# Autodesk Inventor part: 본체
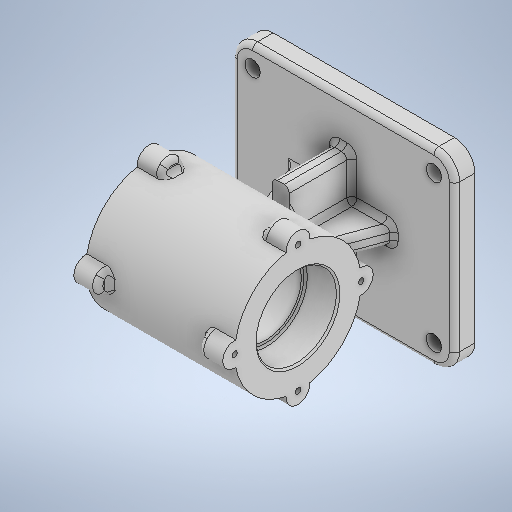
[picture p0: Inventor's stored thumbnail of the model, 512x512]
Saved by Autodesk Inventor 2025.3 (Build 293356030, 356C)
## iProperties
Created: 2025-08
Part Number: 본체
Material: 일반
Document SubType Name: Modeling
Designer: infra011
Density: 1 g/cm^3
Appearance: 기본값
Author: infra011
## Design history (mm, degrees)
sketch "스케치1"
  geometry: L1 (-65, 55)-(65, 55); L2 (65, 55)-(65, -55); L3 (65, -55)-(-65, -55); L4 (-65, -55)-(-65, 55); L5 (-65, 55)-(65, -55); L6 (65, 55)-(-65, -55); 1 further point
  constraints: 12 end point, 2 midpoint, 2 parallel, 1 horizontal, 1 perpendicular
  dimensions: "d0" = 130 distance of L2.end L3.end; "d1" = 110 distance of L1.end L2.end
extrude "돌출1" new body sketch "스케치1" distance "d2" = 12; taper "d3" = 0 deg
sketch "스케치2"
  geometry: L1 (-53, 43)-(53, 43); L2 (53, 43)-(53, -43); L3 (53, -43)-(-53, -43); L4 (-53, -43)-(-53, 43); L5 (-53, 43)-(53, -43); L6 (53, 43)-(-53, -43); 1 further point
  constraints: 12 end point, 2 midpoint, 2 parallel, 1 horizontal, 1 perpendicular
  dimensions: "d4" = 106 distance of L2.end L3.end; "d5" = 86 distance of L1.end L2.end
hole "구멍1" sketch "스케치2" at (-53, 43), (53, -43), (53, 43), (-53, -43) diameter "d6" = 9; stored, may be unused: countersink angle "d10" = 90 deg, drill point angle "d12" = 0 deg; dims "d7" = 8, "d8" = 4, "d9" = 2, "d11" = 12
sketch "스케치3"
  geometry: L1 (43.5, 119)-(-43.5, 119); L2 (-43.5, 119)-(-43.5, 82); L3 (-43.5, 82)-(43.5, 82); L4 (43.5, 82)-(43.5, 119); L5 (43.5, 119)-(-43.5, 82); L6 (-43.5, 119)-(43.5, 82); L7 (65, 0)-(-65, 0) reference; 5 further points
  constraints: 12 end point, 5 midpoint, 2 parallel, 1 horizontal, 1 perpendicular, 1 vertical alignment
  dimensions: "d14" = 37 distance of L1.end L2.end; "d15" = 87 distance of L1.start L1.end; "d16" = 82 distance of point (0, 0) point (0, 82)
revolve "회전1" sketch "스케치3" stored, may be unused: angle "d17" = 90 deg
sketch "스케치4"
  geometry: L1 (43.5, 45)-(43.5, 119) reference; L2 (43.5, 105.5)-(24.5, 105.5); L3 (24.5, 105.5)-(24.5, 82); L4 (24.5, 82)-(43.5, 82); L5 (43.5, 82)-(43.5, 105.5); L6 (24.5, 103)-(-24.5, 103); L7 (-24.5, 103)-(-24.5, 82); L8 (-24.5, 82)-(24.5, 82); L9 (24.5, 82)-(24.5, 103); L10 (-24.5, 105.5)-(-43.5, 105.5); L11 (-43.5, 105.5)-(-43.5, 82); L12 (-43.5, 82)-(-24.5, 82); L13 (-24.5, 82)-(-24.5, 105.5); L14 (-43.5, 45)-(-43.5, 119) reference; L15 (43.5, 45)-(43.5, 119) reference; L16 (-43.5, 45)-(43.5, 45) reference; 4 further points
  constraints: 24 end point, 6 parallel, 3 horizontal, 3 perpendicular, 2 collinear, 2 point on line
  dimensions: "d18" = 19 distance between parallel lines of L5 L9; "d19" = 19 distance between parallel lines of L14 L7; "d20" = 21 distance between parallel lines of L8 L6; "d21" = 23.5 distance between parallel lines of L4 L2; "d22" = 23.5 distance between parallel lines of L12 L10; "d23" = 37 distance between parallel lines of L16 L4; "d24" = 37 distance between parallel lines of L16 L12
revolve "회전2" sketch "스케치4" stored, may be unused: angle "d25" = 90 deg
sketch "스케치5"
  geometry: L1 (0, 0)-(37, 0); C1 r 23.5 at (0, 0) reference; C2 r 7 at (37, 0); C3 r 7 at (0, 37); C4 r 7 at (-37, 0); C5 r 7 at (0, -37); 13 further points
  constraints: 5 coincident, 4 centre point, 2 end point, 1 horizontal, 15 other
  dimensions: "d26" = 14 diameter of C2; "d29" = 360 deg dimension on C1.centre C2.centre (derived)
extrude "돌출2" join sketch "스케치5" distance "d31" = 14; taper "d32" = 0 deg
sketch "스케치6"
  geometry: C1 r 23.5 at (0, 0) reference; C2 r 37 at (0, 0) reference; C3 r 7 at (-37, 0); C4 r 7 at (0, 37); C5 r 7 at (37, 0); C6 r 7 at (0, -37); A1 r 37 centre (0, 0) between (-36.338, 6.969) and (-36.338, -6.969) reference; A2 r 7 centre (-37, 0) between (-36.338, 6.969) and (-36.338, -6.969) reference; A3 r 37 centre (0, 0) between (6.969, 36.338) and (-6.969, 36.338) reference; A4 r 7 centre (0, 37) between (6.969, 36.338) and (-6.969, 36.338) reference; A5 r 37 centre (0, 0) between (36.338, -6.969) and (36.338, 6.969) reference; A6 r 7 centre (37, 0) between (36.338, -6.969) and (36.338, 6.969) reference; A7 r 37 centre (0, 0) between (-6.969, -36.338) and (6.969, -36.338) reference; A8 r 7 centre (0, -37) between (-6.969, -36.338) and (6.969, -36.338) reference; 8 further points
  constraints: 4 centre point, 4 coincident, 1 point on circle
  dimensions: "d33" = 14 diameter of C6; "d34" = 14 diameter of C4; "d35" = 14 diameter of C3; "d36" = 14 diameter of C5
extrude "돌출3" join sketch "스케치6" distance "d37" = 14; taper "d38" = 0 deg
fillet "모깎기1" dims "d39" = 1
chamfer "모따기1" distance "d40" = 1; stored, may be unused: second distance "d41" = 2, angle "d42" = 45 deg
chamfer "모따기2" distance "d43" = 1; stored, may be unused: second distance "d44" = 2, angle "d45" = 45 deg
sketch "스케치7"
  geometry: L1 (43.5, 88.969)-(29.5, 88.969) reference; L2 (29.5, 88.969)-(29.5, 75.031) reference; L3 (29.5, 75.031)-(43.5, 75.031) reference; L4 (43.5, 45.662)-(43.5, 75.031) reference; L5 (43.5, 45.662)-(29.5, 45.662) reference; L6 (29.5, 45.662)-(29.5, 45.662) reference; L7 (29.5, 45.662)-(43.5, 45.662) reference; L8 (43.5, 75.031)-(43.5, 45.662) reference; L9 (43.5, 75.031)-(29.5, 75.031) reference; L10 (29.5, 75.031)-(29.5, 88.969) reference; L11 (29.5, 88.969)-(43.5, 88.969) reference; L12 (43.5, 118.338)-(43.5, 88.969) reference; L13 (43.5, 118.338)-(29.5, 118.338) reference; L14 (29.5, 118.338)-(29.5, 118.338) reference; L15 (29.5, 118.338)-(43.5, 118.338) reference; L16 (43.5, 88.969)-(43.5, 118.338) reference; L17 (-43.5, 45.662)-(-29.5, 45.662) reference; L18 (-29.5, 45.662)-(-29.5, 45.662) reference; L19 (-29.5, 45.662)-(-43.5, 45.662) reference; L20 (-43.5, 45.662)-(-43.5, 75.031) reference; L21 (-43.5, 75.031)-(-29.5, 75.031) reference; L22 (-29.5, 75.031)-(-29.5, 88.969) reference; L23 (-29.5, 88.969)-(-43.5, 88.969) reference; L24 (-43.5, 88.969)-(-43.5, 118.338) reference; L25 (-43.5, 118.338)-(-29.5, 118.338) reference; L26 (-29.5, 118.338)-(-29.5, 118.338) reference; L27 (-29.5, 118.338)-(-43.5, 118.338) reference; L28 (-43.5, 118.338)-(-43.5, 88.969) reference; L29 (-43.5, 88.969)-(-29.5, 88.969) reference; L30 (-29.5, 88.969)-(-29.5, 75.031) reference; L31 (-29.5, 75.031)-(-43.5, 75.031) reference; L32 (-43.5, 75.031)-(-43.5, 45.662) reference; L33 (-29.5, 45)-(29.5, 45) reference; L34 (-65, 0)-(65, 0) reference; L35 (48.5, 12)-(57.5, 12) reference; L36 (-57.5, 12)-(-48.5, 12) reference; L37 (-57.5, 12)-(-48.5, 12) reference; L38 (48.5, 12)-(57.5, 12) reference; L39 (65, 12)-(-65, 12) reference; L40 (-65, 12)-(65, 12) reference; L41 (30, 12)-(17.44, 46.508); L42 (-17.338, 46.787)-(-30, 12); L43 (30, 12)-(-30, 12); L44 (17.44, 46.508)-(-17.338, 46.787); 7 further points
  constraints: 8 end point, 2 midpoint, 2 point on line, 1 collinear, 1 vertical alignment
  dimensions: "d46" = 60 distance of L42.end L41.start; "d47" = 110 deg angle of L39 L41; "d48" = 110 deg angle of L39 L42; "d50" = 30 horizontal distance of point (0, 45) L41.start
extrude "돌출4" join sketch "스케치7" stored distance "d51" = 10; taper "d52" = 0 deg
sketch "스케치9"
  geometry: L1 (-5, -30)-(5, -30); L2 (5, -30)-(5, 30); L3 (5, 30)-(-5, 30); L4 (-5, 30)-(-5, -30); L5 (-65, -55)-(65, -55) reference; 3 further points
  constraints: 8 end point, 2 midpoint, 2 parallel, 1 horizontal, 1 horizontal alignment, 1 perpendicular, 1 vertical alignment
  dimensions: "d59" = 10 distance of L2.end L3.end; "d62" = 60 distance between parallel lines of L3 L1
extrude "돌출6" join sketch "스케치9" distance "d63" = 36.5; taper "d64" = 0 deg
fillet "모깎기2" dims "d65" = 12
fillet "모깎기3" dims "d66" = 3
sketch "스케치10"
  geometry: C1 r 24.5 at (-37, 0) reference; A1 r 37 centre (-37, 0) between (-73.338, -6.969) and (-43.969, -36.338) reference; A2 r 7 centre (-37, -37) between (-43.969, -36.338) and (-30.031, -36.338) reference; A3 r 37 centre (-37, 0) between (-30.031, -36.338) and (-0.662, -6.969) reference; A4 r 7 centre (0, 0) between (-0.662, -6.969) and (-0.662, 6.969) reference; A5 r 37 centre (-37, 0) between (-0.662, 6.969) and (-30.031, 36.338) reference; A6 r 7 centre (-37, 37) between (-30.031, 36.338) and (-43.969, 36.338) reference; A7 r 37 centre (-37, 0) between (-43.969, 36.338) and (-73.338, 6.969) reference; A8 r 7 centre (-74, 0) between (-73.338, 6.969) and (-73.338, -6.969) reference; 1 further point
hole "구멍2" sketch "스케치10" at (-74, 0), (-37, 37), (0, 0), (-37, -37) diameter "d67" = 3.242; stored, may be unused: countersink angle "d71" = 90 deg, drill point angle "d73" = 118 deg; dims "d68" = 8, "d69" = 4, "d70" = 2, "d72" = 10
fillet "모깎기4" dims "d74" = 3
sketch "스케치11"
  geometry: C1 r 24.5 at (37, 0) reference; A1 r 37 centre (37, 0) between (73.338, 6.969) and (43.969, 36.338) reference; A2 r 7 centre (37, 37) between (43.969, 36.338) and (30.031, 36.338) reference; A3 r 37 centre (37, 0) between (30.031, 36.338) and (0.662, 6.969) reference; A4 r 7 centre (0, 0) between (0.662, 6.969) and (0.662, -6.969) reference; A5 r 37 centre (37, 0) between (0.662, -6.969) and (30.031, -36.338) reference; A6 r 7 centre (37, -37) between (30.031, -36.338) and (43.969, -36.338) reference; A7 r 37 centre (37, 0) between (43.969, -36.338) and (73.338, -6.969) reference; A8 r 7 centre (74, 0) between (73.338, -6.969) and (73.338, 6.969) reference; 1 further point
hole "구멍3" sketch "스케치11" at (37, -37), (0, 0), (37, 37), (74, 0) diameter "d75" = 3.242; stored, may be unused: countersink angle "d79" = 90 deg, drill point angle "d81" = 118 deg; dims "d76" = 8, "d77" = 4, "d78" = 2, "d80" = 10
node "솔리드1"
node "투영된 루프1"
node "투영된 루프2"
node "스케치 - 원형 패턴1" dims "d29" = 360 deg (derived)
node "투영된 루프3"
node "투영된 루프4"
node "투영된 루프5"
node "투영된 루프6"
node "투영된 루프7"
node "투영된 루프8"
node "투영된 루프9"
node "투영된 루프10"
feature "A9D066F2-1C7D-4E18-AEED-F7BC21143FA4" dims "d6" = 9, "d7" = 8, "d8" = 4, "d9" = 2, "d10" = 90 deg, "d11" = 12, "d12" = 0
